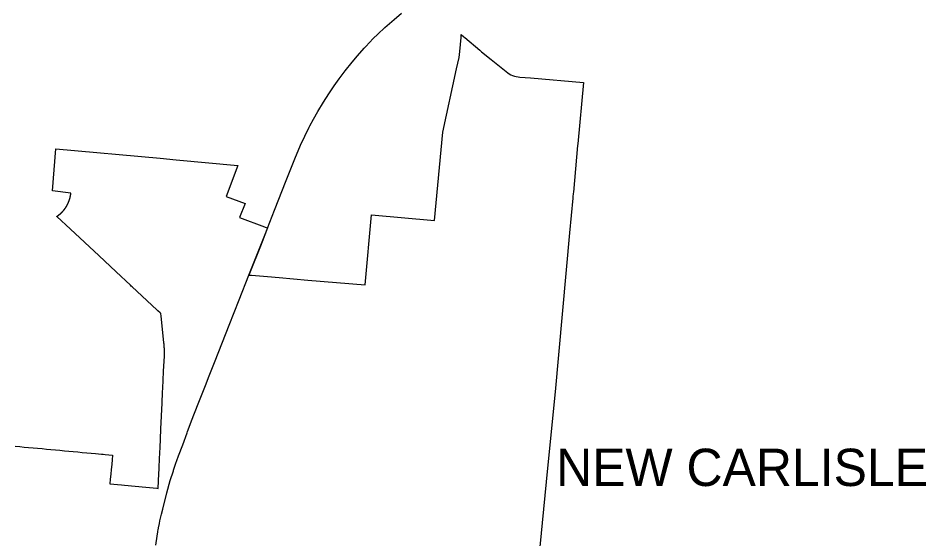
# Model space of a CAD drawing. Extents: x 0 to 34, y 0 to 22.
# Drawn here: x 6.046 to 6.2413, y 16.2407 to 16.3528 of the extents above; entities that cross this region are included whole.
import ezdxf

# ---------------------------------------------------------------- set-up
doc = ezdxf.new("R2010")
doc.units = 0
for name, color, linetype in [('GM_X_Corporation', 7, 'Continuous'), ('GM_X_Corporation_Text', 7, 'Continuous'), ('GM_X_State_Route', 7, 'Continuous')]:
    doc.layers.add(name, color=color, linetype=linetype)

msp = doc.modelspace()

# ---------------------------------------------------------------- linework, layer by layer
at = {"layer": 'GM_X_Corporation'}
msp.add_lwpolyline([(6.04537, 16.26065), (6.04633, 16.26056), (6.04729, 16.26047), (6.04825, 16.26038), (6.04921, 16.2603), (6.05017, 16.26021), (6.05113, 16.26012), (6.0521, 16.26003), (6.05306, 16.25994), (6.05402, 16.25985), (6.05498, 16.25976), (6.05594, 16.25968), (6.0569, 16.25959), (6.05786, 16.2595), (6.05882, 16.25941), (6.05978, 16.25932), (6.06074, 16.25923), (6.0617, 16.25914), (6.06266, 16.25906), (6.06391, 16.25894), (6.06431, 16.2589), (6.06471, 16.25887), (6.06631, 16.25872), (6.06621, 16.25769), (6.06612, 16.25675), (6.06612, 16.25667), (6.06602, 16.25565), (6.06592, 16.25462), (6.06582, 16.25357), (6.06573, 16.25254), (6.06821, 16.25231), (6.06891, 16.25224), (6.07349, 16.2518), (6.07582, 16.25158), (6.07615, 16.25155), (6.0762, 16.25316), (6.07621, 16.25329), (6.07633, 16.25594), (6.07634, 16.25605), (6.07643, 16.2579), (6.07649, 16.25921), (6.07654, 16.26036), (6.07663, 16.26218), (6.07673, 16.26442), (6.07698, 16.26992), (6.07708, 16.27227), (6.07712, 16.27313), (6.07713, 16.27325), (6.0772, 16.27478), (6.0772, 16.27478), (6.0773, 16.27679), (6.07745, 16.28004), (6.07746, 16.28041), (6.07746, 16.28043), (6.07746, 16.28044), (6.07746, 16.28046), (6.07746, 16.28048), (6.07746, 16.28049), (6.07747, 16.28051), (6.07747, 16.28052), (6.07747, 16.28054), (6.07747, 16.28055), (6.07747, 16.28057), (6.07747, 16.28059), (6.07747, 16.2806), (6.07747, 16.28062), (6.07747, 16.28063), (6.07747, 16.28065), (6.07747, 16.28066), (6.07747, 16.28068), (6.07747, 16.2807), (6.07747, 16.28071), (6.07747, 16.28073), (6.07747, 16.28074), (6.07747, 16.28076), (6.07747, 16.28077), (6.07747, 16.28079), (6.07747, 16.28081), (6.07747, 16.28082), (6.07747, 16.28084), (6.07747, 16.28085), (6.07747, 16.28087), (6.07747, 16.28089), (6.07747, 16.2809), (6.07747, 16.28092), (6.07747, 16.28093), (6.07747, 16.28095), (6.07747, 16.28096), (6.07747, 16.28098), (6.07747, 16.281), (6.07747, 16.28101), (6.07747, 16.28103), (6.07747, 16.28104), (6.07747, 16.28106), (6.07747, 16.28107), (6.07747, 16.28109), (6.07747, 16.28111), (6.07747, 16.28112), (6.07747, 16.28114), (6.07747, 16.28115), (6.07747, 16.28117), (6.07747, 16.28118), (6.07747, 16.2812), (6.07747, 16.28122), (6.07747, 16.28123), (6.07746, 16.28125), (6.07746, 16.28126), (6.07746, 16.28128), (6.07746, 16.28129), (6.07746, 16.28131), (6.07746, 16.28133), (6.07746, 16.28134), (6.07746, 16.28136), (6.07746, 16.28137), (6.07746, 16.28139), (6.07746, 16.2814), (6.07746, 16.28142), (6.07746, 16.28144), (6.07746, 16.28145), (6.07746, 16.28147), (6.07746, 16.28148), (6.07746, 16.2815), (6.07746, 16.28151), (6.07746, 16.28153), (6.07746, 16.28155), (6.07746, 16.28156), (6.07746, 16.28158), (6.07746, 16.28159), (6.07745, 16.28161), (6.07745, 16.28162), (6.07745, 16.28164), (6.07745, 16.28166), (6.07745, 16.28167), (6.07745, 16.28169), (6.07745, 16.2817), (6.07745, 16.28172), (6.07745, 16.28173), (6.07745, 16.28175), (6.07745, 16.28177), (6.07745, 16.28178), (6.07745, 16.2818), (6.07745, 16.28181), (6.07744, 16.28183), (6.07744, 16.28184), (6.07744, 16.28186), (6.07744, 16.28188), (6.07744, 16.28189), (6.07744, 16.28191), (6.07744, 16.28192), (6.07744, 16.28194), (6.07744, 16.28195), (6.07744, 16.28197), (6.07744, 16.28199), (6.07744, 16.282), (6.07743, 16.28202), (6.07743, 16.28203), (6.07743, 16.28205), (6.07743, 16.28206), (6.07743, 16.28208), (6.07743, 16.2821), (6.07743, 16.28211), (6.07743, 16.28213), (6.07743, 16.28214), (6.07743, 16.28216), (6.07742, 16.28217), (6.07742, 16.28219), (6.07742, 16.28221), (6.07742, 16.28222), (6.07742, 16.28224), (6.07742, 16.28225), (6.07742, 16.28227), (6.07742, 16.28228), (6.07742, 16.2823), (6.07741, 16.28232), (6.07741, 16.28233), (6.07741, 16.28235), (6.07741, 16.28236), (6.07741, 16.28238), (6.07741, 16.28239), (6.07741, 16.28241), (6.07741, 16.28243), (6.0774, 16.28244), (6.0774, 16.28246), (6.0774, 16.28247), (6.0774, 16.28249), (6.0774, 16.2825), (6.0774, 16.28252), (6.0774, 16.28254), (6.0774, 16.28255), (6.07739, 16.28257), (6.07739, 16.28258), (6.07739, 16.2826), (6.07739, 16.28261), (6.07739, 16.28263), (6.07739, 16.28264), (6.07739, 16.28266), (6.07738, 16.28268), (6.07738, 16.28269), (6.07738, 16.28271), (6.07738, 16.28272), (6.07738, 16.28274), (6.07738, 16.28275), (6.07738, 16.28277), (6.07737, 16.28279), (6.07737, 16.2828), (6.07737, 16.28282), (6.07737, 16.28283), (6.07737, 16.28284), (6.07737, 16.28285), (6.07737, 16.28286), (6.07736, 16.28288), (6.07736, 16.28289), (6.07736, 16.2829), (6.07736, 16.28291), (6.07736, 16.28292), (6.07736, 16.28294), (6.07736, 16.28295), (6.07674, 16.28865), (6.07668, 16.28921), (6.07652, 16.28936), (6.07603, 16.28982), (6.07588, 16.28995), (6.07258, 16.29304), (6.0705, 16.29498), (6.07034, 16.29513), (6.07015, 16.29531), (6.06706, 16.2982), (6.06332, 16.3017), (6.05725, 16.30738), (6.05432, 16.31015), (6.05433, 16.31016), (6.05434, 16.31016), (6.05436, 16.31017), (6.05437, 16.31018), (6.05438, 16.31019), (6.0544, 16.3102), (6.05441, 16.31021), (6.05442, 16.31022), (6.05443, 16.31023), (6.05445, 16.31023), (6.05446, 16.31024), (6.05447, 16.31025), (6.05449, 16.31026), (6.0545, 16.31027), (6.05451, 16.31028), (6.05452, 16.31029), (6.05454, 16.3103), (6.05455, 16.31031), (6.05456, 16.31032), (6.05458, 16.31033), (6.05459, 16.31033), (6.0546, 16.31034), (6.05461, 16.31035), (6.05463, 16.31036), (6.05464, 16.31037), (6.05465, 16.31038), (6.05466, 16.31039), (6.05468, 16.3104), (6.05469, 16.31041), (6.0547, 16.31042), (6.05471, 16.31043), (6.05473, 16.31044), (6.05474, 16.31045), (6.05475, 16.31046), (6.05477, 16.31047), (6.05478, 16.31048), (6.05479, 16.31049), (6.0548, 16.3105), (6.05481, 16.31051), (6.05483, 16.31052), (6.05484, 16.31053), (6.05485, 16.31054), (6.05486, 16.31055), (6.05488, 16.31056), (6.05489, 16.31057), (6.0549, 16.31058), (6.05491, 16.31059), (6.05493, 16.3106), (6.05494, 16.31061), (6.05495, 16.31062), (6.05496, 16.31063), (6.05497, 16.31064), (6.05499, 16.31065), (6.055, 16.31066), (6.05501, 16.31067), (6.05502, 16.31068), (6.05503, 16.31069), (6.05503, 16.31069), (6.05505, 16.3107), (6.05506, 16.31071), (6.05507, 16.31072), (6.05508, 16.31073), (6.05509, 16.31074), (6.05511, 16.31075), (6.05512, 16.31076), (6.05513, 16.31078), (6.05514, 16.31079), (6.05515, 16.3108), (6.05516, 16.31081), (6.05518, 16.31082), (6.05519, 16.31083), (6.0552, 16.31084), (6.05521, 16.31085), (6.05522, 16.31086), (6.05523, 16.31087), (6.05525, 16.31088), (6.05526, 16.31089), (6.05527, 16.3109), (6.05528, 16.31092), (6.05529, 16.31093), (6.0553, 16.31094), (6.05531, 16.31095), (6.05533, 16.31096), (6.05534, 16.31097), (6.05535, 16.31098), (6.05536, 16.31099), (6.05537, 16.311), (6.05538, 16.31102), (6.05539, 16.31103), (6.0554, 16.31104), (6.05542, 16.31105), (6.05543, 16.31106), (6.05544, 16.31107), (6.05545, 16.31108), (6.05546, 16.3111), (6.05547, 16.31111), (6.05548, 16.31112), (6.05549, 16.31113), (6.0555, 16.31114), (6.05552, 16.31115), (6.05553, 16.31116), (6.05554, 16.31118), (6.05555, 16.31119), (6.05556, 16.3112), (6.05557, 16.31121), (6.05558, 16.31122), (6.05559, 16.31123), (6.0556, 16.31125), (6.05561, 16.31126), (6.05562, 16.31127), (6.05563, 16.31128), (6.05564, 16.31129), (6.05565, 16.3113), (6.05567, 16.31132), (6.05568, 16.31133), (6.05569, 16.31134), (6.0557, 16.31135), (6.05571, 16.31136), (6.05572, 16.31138), (6.05573, 16.31139), (6.05574, 16.3114), (6.05575, 16.31141), (6.05576, 16.31142), (6.05577, 16.31144), (6.05578, 16.31145), (6.05579, 16.31146), (6.0558, 16.31147), (6.05581, 16.31149), (6.05582, 16.3115), (6.05583, 16.31151), (6.05583, 16.31151), (6.05584, 16.31152), (6.05585, 16.31153), (6.05586, 16.31155), (6.05587, 16.31156), (6.05588, 16.31157), (6.05589, 16.31158), (6.0559, 16.3116), (6.05591, 16.31161), (6.05592, 16.31162), (6.05593, 16.31163), (6.05594, 16.31165), (6.05595, 16.31166), (6.05596, 16.31167), (6.05597, 16.31168), (6.05598, 16.3117), (6.05599, 16.31171), (6.056, 16.31172), (6.05601, 16.31173), (6.05602, 16.31175), (6.05603, 16.31176), (6.05603, 16.31177), (6.05604, 16.31179), (6.05605, 16.3118), (6.05606, 16.31181), (6.05607, 16.31182), (6.05608, 16.31184), (6.05609, 16.31185), (6.0561, 16.31186), (6.05611, 16.31188), (6.05612, 16.31189), (6.05613, 16.3119), (6.05614, 16.31191), (6.05615, 16.31193), (6.05615, 16.31194), (6.05616, 16.31195), (6.05617, 16.31196), (6.05617, 16.31197), (6.05618, 16.31198), (6.05619, 16.31199), (6.0562, 16.31201), (6.05621, 16.31202), (6.05622, 16.31203), (6.05623, 16.31205), (6.05623, 16.31206), (6.05624, 16.31207), (6.05625, 16.31209), (6.05626, 16.3121), (6.05627, 16.31211), (6.05628, 16.31213), (6.05629, 16.31214), (6.0563, 16.31215), (6.0563, 16.31217), (6.05631, 16.31218), (6.05632, 16.31219), (6.05633, 16.31221), (6.05634, 16.31222), (6.05635, 16.31223), (6.05635, 16.31225), (6.05636, 16.31226), (6.05637, 16.31227), (6.05638, 16.31229), (6.05639, 16.3123), (6.0564, 16.31231), (6.0564, 16.31233), (6.05641, 16.31234), (6.05642, 16.31235), (6.05643, 16.31237), (6.05644, 16.31238), (6.05644, 16.3124), (6.05645, 16.31241), (6.05646, 16.31242), (6.05647, 16.31244), (6.05647, 16.31244), (6.05648, 16.31245), (6.05648, 16.31246), (6.05649, 16.31248), (6.0565, 16.31249), (6.05651, 16.31251), (6.05652, 16.31252), (6.05652, 16.31253), (6.05653, 16.31255), (6.05654, 16.31256), (6.05655, 16.31258), (6.05655, 16.31259), (6.05656, 16.3126), (6.05657, 16.31262), (6.05658, 16.31263), (6.05658, 16.31265), (6.05659, 16.31266), (6.0566, 16.31267), (6.05661, 16.31269), (6.05661, 16.3127), (6.05662, 16.31272), (6.05663, 16.31273), (6.05663, 16.31274), (6.05664, 16.31276), (6.05665, 16.31277), (6.05666, 16.31279), (6.05666, 16.3128), (6.05667, 16.31282), (6.05668, 16.31283), (6.05668, 16.31284), (6.05669, 16.31286), (6.0567, 16.31287), (6.0567, 16.31289), (6.05671, 16.3129), (6.05672, 16.31292), (6.05672, 16.31293), (6.05673, 16.31294), (6.05673, 16.31295), (6.05674, 16.31296), (6.05674, 16.31297), (6.05675, 16.31299), (6.05676, 16.313), (6.05676, 16.31302), (6.05677, 16.31303), (6.05678, 16.31305), (6.05678, 16.31306), (6.05679, 16.31307), (6.0568, 16.31309), (6.0568, 16.3131), (6.05681, 16.31312), (6.05682, 16.31313), (6.05682, 16.31315), (6.05683, 16.31316), (6.05683, 16.31318), (6.05684, 16.31319), (6.05685, 16.31321), (6.05685, 16.31322), (6.05686, 16.31324), (6.05686, 16.31325), (6.05687, 16.31326), (6.05688, 16.31328), (6.05688, 16.31329), (6.05689, 16.31331), (6.05689, 16.31332), (6.0569, 16.31334), (6.05691, 16.31335), (6.05691, 16.31337), (6.05692, 16.31338), (6.05692, 16.3134), (6.05693, 16.31341), (6.05693, 16.31343), (6.05694, 16.31344), (6.05694, 16.31346), (6.05695, 16.31347), (6.05695, 16.31348), (6.05696, 16.31349), (6.05696, 16.3135), (6.05697, 16.31352), (6.05697, 16.31353), (6.05698, 16.31355), (6.05698, 16.31356), (6.05699, 16.31358), (6.05699, 16.31359), (6.057, 16.31361), (6.057, 16.31362), (6.05701, 16.31364), (6.05701, 16.31365), (6.05702, 16.31367), (6.05702, 16.31368), (6.05703, 16.3137), (6.05703, 16.31371), (6.05704, 16.31373), (6.05704, 16.31374), (6.05705, 16.31376), (6.05705, 16.31377), (6.05706, 16.31379), (6.05706, 16.3138), (6.05707, 16.31382), (6.05707, 16.31383), (6.05708, 16.31385), (6.05708, 16.31386), (6.05708, 16.31388), (6.05709, 16.31389), (6.05709, 16.31391), (6.0571, 16.31392), (6.0571, 16.31394), (6.05711, 16.31396), (6.05711, 16.31397), (6.05712, 16.31399), (6.05712, 16.314), (6.05712, 16.31402), (6.05712, 16.31402), (6.05713, 16.31403), (6.05713, 16.31405), (6.05714, 16.31406), (6.05714, 16.31408), (6.05714, 16.31409), (6.05715, 16.31411), (6.05715, 16.31412), (6.05716, 16.31414), (6.05716, 16.31415), (6.05716, 16.31417), (6.05717, 16.31419), (6.05717, 16.3142), (6.05718, 16.31422), (6.05718, 16.31423), (6.05718, 16.31425), (6.05719, 16.31426), (6.05719, 16.31428), (6.05719, 16.31429), (6.0572, 16.31431), (6.0572, 16.31432), (6.0572, 16.31434), (6.05721, 16.31436), (6.05721, 16.31437), (6.05721, 16.31439), (6.05722, 16.3144), (6.05722, 16.31442), (6.05722, 16.31443), (6.05723, 16.31445), (6.05723, 16.31446), (6.05723, 16.31448), (6.05724, 16.3145), (6.05724, 16.31451), (6.05724, 16.31453), (6.05725, 16.31454), (6.05725, 16.31456), (6.05725, 16.31457), (6.05725, 16.31457), (6.05725, 16.31459), (6.05726, 16.3146), (6.05726, 16.31462), (6.05726, 16.31464), (6.05727, 16.31465), (6.05727, 16.31467), (6.05727, 16.31468), (6.05727, 16.3147), (6.05728, 16.31471), (6.05728, 16.31473), (6.05728, 16.31475), (6.05728, 16.31476), (6.05729, 16.31478), (6.05729, 16.31479), (6.05729, 16.31481), (6.05729, 16.31482), (6.0573, 16.31484), (6.0573, 16.31486), (6.0573, 16.31487), (6.0573, 16.31489), (6.0573, 16.3149), (6.05731, 16.31492), (6.05731, 16.31493), (6.05731, 16.31495), (6.05731, 16.31497), (6.05731, 16.31498), (6.05732, 16.315), (6.05732, 16.31501), (6.05732, 16.31503), (6.05732, 16.31504), (6.05732, 16.31506), (6.05733, 16.31508), (6.05733, 16.31509), (6.05733, 16.31511), (6.05733, 16.31512), (6.05733, 16.31514), (6.05335, 16.31564), (6.05409, 16.32468), (6.07653, 16.32266), (6.07997, 16.32235), (6.09327, 16.3211), (6.09073, 16.31443), (6.09482, 16.31292), (6.09363, 16.30993), (6.09902, 16.3079), (6.09917, 16.30785), (6.09966, 16.30766), (6.09849, 16.30467), (6.09826, 16.3041), (6.09566, 16.29751), (6.09622, 16.29746), (6.09966, 16.29717), (6.10216, 16.29696), (6.10836, 16.29643), (6.12063, 16.29539), (6.12203, 16.31048), (6.13559, 16.30924), (6.13737, 16.32831), (6.14035, 16.34195), (6.14088, 16.34438), (6.141, 16.34565), (6.14129, 16.34871), (6.14134, 16.34929), (6.14188, 16.34884), (6.14211, 16.34866), (6.14533, 16.34595), (6.14572, 16.34562), (6.14775, 16.34391), (6.15102, 16.34133), (6.15134, 16.34108), (6.15168, 16.34086), (6.15203, 16.34067), (6.15239, 16.3405), (6.15277, 16.34037), (6.15315, 16.34026), (6.15356, 16.34018), (6.15397, 16.34014), (6.15622, 16.33999), (6.16763, 16.33897), (6.16642, 16.32577), (6.16639, 16.32545), (6.16546, 16.31534), (6.16544, 16.31507), (6.16537, 16.31438), (6.16534, 16.31406), (6.16466, 16.30659), (6.16152, 16.27237), (6.15991, 16.2559), (6.15738, 16.23013)], dxfattribs=at)
at = {"layer": 'GM_X_State_Route'}
for points in [[(6.10877, 16.32963), (6.10957, 16.33111), (6.11048, 16.33272), (6.11169, 16.33477), (6.11282, 16.33655), (6.114, 16.3383), (6.11509, 16.3398), (6.11636, 16.34148), (6.11784, 16.34334), (6.11903, 16.34475), (6.12048, 16.34636), (6.1208, 16.34671), (6.12242, 16.34845), (6.12336, 16.34938), (6.12491, 16.3508), (6.12689, 16.35255), (6.12851, 16.35391)], [(6.09965, 16.30761), (6.10118, 16.31148), (6.10368, 16.31786), (6.10552, 16.32252), (6.10675, 16.32549), (6.10765, 16.32745), (6.1086, 16.32933), (6.10877, 16.32963)], [(6.09566, 16.29749), (6.09934, 16.30682), (6.09965, 16.30761)], [(6.08839, 16.279), (6.09142, 16.28673), (6.09357, 16.2922), (6.09566, 16.29749)], [(6.08256, 16.26414), (6.0833, 16.26609), (6.08474, 16.26977), (6.08646, 16.27411), (6.08698, 16.27541), (6.08839, 16.279)], [(6.07995, 16.25701), (6.08015, 16.25756), (6.08051, 16.25855), (6.0814, 16.26097), (6.08233, 16.26354), (6.08244, 16.26381), (6.08256, 16.26414)], [(6.07941, 16.25545), (6.07973, 16.25638), (6.07995, 16.25701)], [(6.07619, 16.24308), (6.07638, 16.24403), (6.0765, 16.24458), (6.07684, 16.24602), (6.07711, 16.2471), (6.07801, 16.25062), (6.07873, 16.25323), (6.07939, 16.25536), (6.07941, 16.25545)], [(6.07562, 16.23931), (6.07588, 16.24129), (6.07602, 16.24218), (6.07614, 16.24281), (6.07616, 16.24295), (6.07619, 16.24308)]]:
    msp.add_lwpolyline(points, dxfattribs=at)

# ---------------------------------------------------------------- texts
at = {"layer": 'GM_X_Corporation_Text'}
msp.add_text('NEW CARLISLE', height=0.008037, rotation=0, dxfattribs=at).set_placement((6.16175, 16.25207))

doc.saveas('drawing.dxf')
